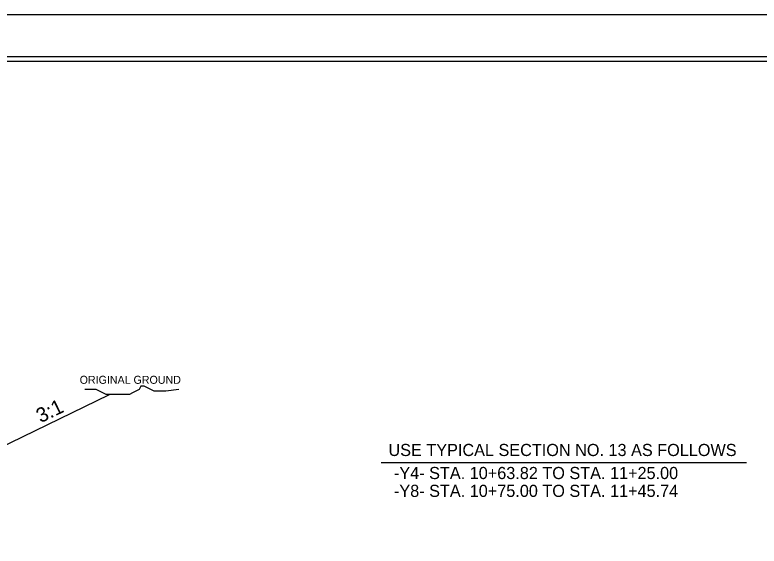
# Model space of a CAD drawing. Extents: x 958711 to 962106, y 831169 to 840840.
# Drawn here: x 959716.7 to 960115.9, y 834433 to 834718.1 of the extents above; entities that cross this region are included whole.
import ezdxf

# ---------------------------------------------------------------- set-up
doc = ezdxf.new("R2010")
doc.units = 0
for name, color, linetype in [('Old_Level_1', 7, 'Continuous'), ('Old_Level_21', 7, 'Continuous'), ('Sheet Plot Border Inside CELL', 7, 'Continuous'), ('Sheet Plot Border Outside CELL', 7, 'Continuous'), ('Sheet Typical CELL', 7, 'Continuous')]:
    doc.layers.add(name, color=color, linetype=linetype)

msp = doc.modelspace()

# ---------------------------------------------------------------- linework, layer by layer
at = {"layer": 'Old_Level_1'}
for p, q in [((959705.35, 834484.24), (959767.49, 834514.33)), ((959913.14, 834477.81), (960109.08, 834477.81))]:
    msp.add_line(p, q, dxfattribs=at)
at = {"layer": 'Old_Level_21'}
msp.add_lwpolyline([(959804.73, 834516.98), (959797.64, 834516.1), (959795.86, 834516.1), (959793.21, 834516.1), (959791.43, 834516.1), (959789.66, 834516.98), (959787.88, 834517.88), (959786.11, 834518.76), (959784.33, 834518.76), (959783.44, 834516.98), (959781.68, 834516.1), (959779.9, 834515.21), (959778.13, 834514.33), (959776.35, 834514.33), (959774.58, 834514.33), (959772.81, 834514.33), (959771.04, 834514.33), (959769.26, 834514.33), (959767.49, 834514.33), (959765.71, 834514.33), (959763.94, 834515.21), (959762.17, 834516.1), (959760.4, 834516.98), (959757.73, 834516.98), (959755.96, 834516.98), (959754.18, 834516.98)], dxfattribs=at)
at = {"layer": 'Sheet Plot Border Inside CELL'}
msp.add_lwpolyline([(960390.3, 834695.64), (958723.8, 834695.64), (958723.8, 833640.54), (960390.3, 833640.54)], close=True, dxfattribs=at)
at = {"layer": 'Sheet Plot Border Outside CELL'}
msp.add_lwpolyline([(960394.8, 834718.09), (958710.8, 834718.09), (958710.8, 833618.09), (960394.8, 833618.09)], close=True, dxfattribs=at)
at = {"layer": 'Sheet Typical CELL'}
msp.add_lwpolyline([(960377.8, 834693.09), (958877.8, 834693.09), (958877.8, 833643.09), (960377.8, 833643.09)], close=True, dxfattribs=at)

# ---------------------------------------------------------------- texts
at = {"layer": 'Old_Level_1'}
msp.add_text('3:1', height=7.801, rotation=25.8427, dxfattribs=at).set_placement((959730.54, 834498.9))
for s, p in [('USE TYPICAL SECTION NO. 13 AS FOLLOWS', (959917.08, 834481.33)), ('-Y4- STA. 10+63.82 TO STA. 11+25.00', (959920.03, 834468.97)), ('-Y8- STA. 10+75.00 TO STA. 11+45.74', (959920.03, 834459.39))]:
    msp.add_text(s, height=6.5088, dxfattribs=at).set_placement(p)
at = {"layer": 'Old_Level_21'}
msp.add_text('ORIGINAL GROUND', height=4.2722, dxfattribs=at).set_placement((959751.48, 834520.1))

doc.saveas('drawing.dxf')
